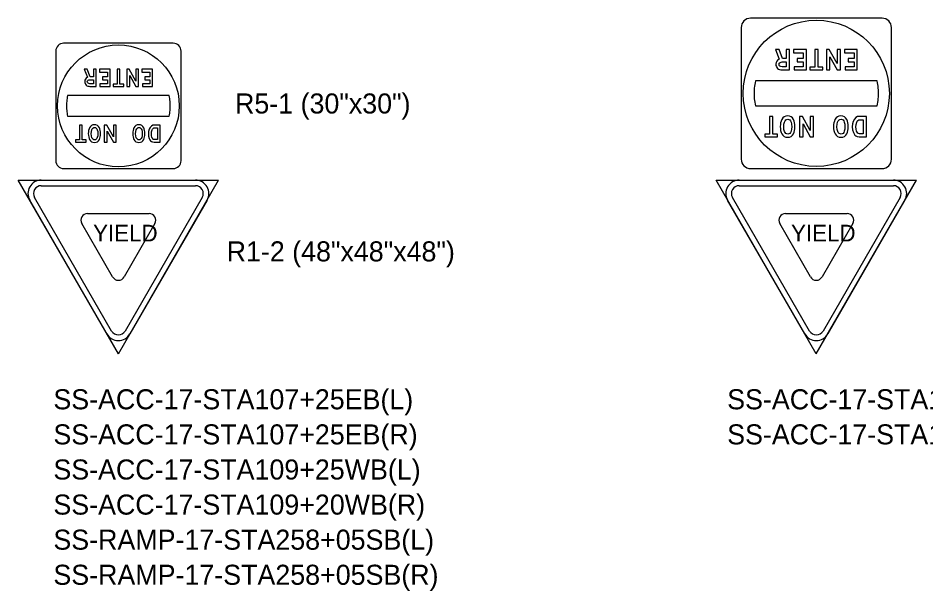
# Model space of a CAD drawing. Extents: x 620856.8 to 620948.6, y 415598.8 to 415658.2.
# Drawn here: x 620859.34 to 620877.45, y 415616.28 to 415627.7 of the extents above; entities that cross this region are included whole.
import ezdxf

# ---------------------------------------------------------------- set-up
doc = ezdxf.new("R2010")
doc.units = 0
doc.layers.add('SIGNS', color=7, linetype='Continuous')

msp = doc.modelspace()

# ---------------------------------------------------------------- linework, layer by layer
at = {"layer": 'SIGNS'}
for p, q in [((620876.575, 415627.702), (620873.95, 415627.702)), ((620876.575, 415627.702), (620873.95, 415627.702)), ((620873.762, 415627.514), (620873.762, 415624.889)), ((620873.762, 415627.514), (620873.762, 415624.889)), ((620876.762, 415624.889), (620876.762, 415627.514)), ((620876.762, 415624.889), (620876.762, 415627.514)), ((620862.431, 415627.202), (620860.243, 415627.202)), ((620862.431, 415627.202), (620860.243, 415627.202)), ((620860.087, 415627.045), (620860.087, 415624.858)), ((620860.087, 415627.045), (620860.087, 415624.858)), ((620862.587, 415624.858), (620862.587, 415627.045)), ((620862.587, 415624.858), (620862.587, 415627.045)), ((620874.046, 415626.45), (620874.04, 415626.415)), ((620876.478, 415626.45), (620874.046, 415626.45)), ((620876.485, 415626.415), (620876.478, 415626.45)), ((620874.023, 415626.273), (620874.022, 415626.237)), ((620874.025, 415626.308), (620874.023, 415626.273)), ((620874.029, 415626.344), (620874.025, 415626.308)), ((620874.034, 415626.379), (620874.029, 415626.344)), ((620874.04, 415626.415), (620874.034, 415626.379)), ((620876.491, 415626.379), (620876.485, 415626.415)), ((620876.496, 415626.344), (620876.491, 415626.379)), ((620876.499, 415626.308), (620876.496, 415626.344)), ((620876.502, 415626.273), (620876.499, 415626.308)), ((620876.503, 415626.237), (620876.502, 415626.273)), ((620860.313, 415626.1), (620860.309, 415626.071)), ((620860.318, 415626.129), (620860.313, 415626.1)), ((620860.323, 415626.158), (620860.318, 415626.129)), ((620862.35, 415626.158), (620860.323, 415626.158)), ((620862.356, 415626.129), (620862.35, 415626.158)), ((620862.36, 415626.1), (620862.356, 415626.129)), ((620862.365, 415626.071), (620862.36, 415626.1)), ((620874.022, 415626.237), (620874.021, 415626.202)), ((620874.021, 415626.202), (620874.022, 415626.166)), ((620874.022, 415626.166), (620874.023, 415626.13)), ((620874.023, 415626.13), (620874.025, 415626.095)), ((620874.025, 415626.095), (620874.029, 415626.059)), ((620876.496, 415626.059), (620876.499, 415626.095)), ((620876.499, 415626.095), (620876.502, 415626.13)), ((620876.502, 415626.13), (620876.503, 415626.166)), ((620876.504, 415626.201), (620876.503, 415626.237)), ((620876.503, 415626.166), (620876.504, 415626.201)), ((620860.304, 415626.011), (620860.303, 415625.981)), ((620860.303, 415625.981), (620860.303, 415625.952)), ((620860.303, 415625.952), (620860.303, 415625.922)), ((620860.303, 415625.922), (620860.304, 415625.892)), ((620860.306, 415626.041), (620860.304, 415626.011)), ((620860.309, 415626.071), (620860.306, 415626.041)), ((620862.368, 415626.041), (620862.365, 415626.071)), ((620862.37, 415626.011), (620862.368, 415626.041)), ((620862.371, 415625.981), (620862.37, 415626.011)), ((620862.37, 415625.892), (620862.371, 415625.922)), ((620862.371, 415625.951), (620862.371, 415625.981)), ((620862.371, 415625.922), (620862.371, 415625.951)), ((620874.029, 415626.059), (620874.034, 415626.024)), ((620874.034, 415626.024), (620874.04, 415625.988)), ((620874.04, 415625.988), (620874.046, 415625.954)), ((620874.046, 415625.954), (620876.478, 415625.954)), ((620876.478, 415625.954), (620876.485, 415625.988)), ((620876.485, 415625.988), (620876.491, 415626.024)), ((620876.491, 415626.024), (620876.496, 415626.059)), ((620860.304, 415625.892), (620860.306, 415625.863)), ((620860.306, 415625.863), (620860.309, 415625.833)), ((620860.309, 415625.833), (620860.313, 415625.804)), ((620860.313, 415625.804), (620860.318, 415625.774)), ((620860.318, 415625.774), (620860.323, 415625.745)), ((620860.323, 415625.745), (620862.35, 415625.745)), ((620862.35, 415625.745), (620862.356, 415625.774)), ((620862.356, 415625.774), (620862.36, 415625.804)), ((620862.36, 415625.804), (620862.365, 415625.833)), ((620862.365, 415625.833), (620862.368, 415625.863)), ((620862.368, 415625.863), (620862.37, 415625.892)), ((620860.243, 415624.702), (620862.431, 415624.702)), ((620860.243, 415624.702), (620862.431, 415624.702)), ((620873.95, 415624.702), (620876.575, 415624.702)), ((620873.95, 415624.702), (620876.575, 415624.702)), ((620859.337, 415624.471), (620863.337, 415624.471)), ((620861.337, 415621.007), (620859.337, 415624.471)), ((620859.799, 415624.471), (620862.875, 415624.471)), ((620861.337, 415621.007), (620863.337, 415624.471)), ((620873.262, 415624.471), (620877.262, 415624.471)), ((620875.262, 415621.007), (620873.262, 415624.471)), ((620873.724, 415624.471), (620876.8, 415624.471)), ((620875.262, 415621.007), (620877.262, 415624.471)), ((620859.799, 415624.36), (620862.875, 415624.36)), ((620873.724, 415624.36), (620876.8, 415624.36)), ((620861.202, 415621.462), (620859.664, 415624.126)), ((620863.01, 415624.126), (620861.472, 415621.462)), ((620875.128, 415621.462), (620873.59, 415624.126)), ((620876.935, 415624.126), (620875.397, 415621.462)), ((620861.106, 415621.407), (620859.568, 415624.071)), ((620863.106, 415624.071), (620861.568, 415621.407)), ((620875.031, 415621.407), (620873.493, 415624.071)), ((620877.031, 415624.071), (620875.493, 415621.407)), ((620860.722, 415623.804), (620861.951, 415623.804)), ((620874.648, 415623.804), (620875.877, 415623.804)), ((620861.221, 415622.54), (620860.607, 415623.604)), ((620862.067, 415623.604), (620861.452, 415622.54)), ((620875.147, 415622.54), (620874.533, 415623.604)), ((620875.992, 415623.604), (620875.378, 415622.54))]:
    msp.add_line(p, q, dxfattribs=at)
for points in [[(620874.727, 415627.077), (620874.663, 415627.077), (620874.663, 415626.897), (620874.585, 415626.897), (620874.518, 415627.077), (620874.447, 415627.077), (620874.52, 415626.886), (620874.494, 415626.868), (620874.473, 415626.843), (620874.46, 415626.814), (620874.456, 415626.783), (620874.458, 415626.759), (620874.465, 415626.737), (620874.476, 415626.718), (620874.491, 415626.7), (620874.51, 415626.686), (620874.531, 415626.676), (620874.554, 415626.67), (620874.579, 415626.668), (620874.727, 415626.668), (620874.727, 415627.077)], [(620874.663, 415626.828), (620874.663, 415626.732), (620874.578, 415626.732), (620874.555, 415626.735), (620874.536, 415626.745), (620874.523, 415626.76), (620874.519, 415626.78), (620874.524, 415626.801), (620874.538, 415626.817), (620874.558, 415626.826), (620874.581, 415626.828), (620874.663, 415626.828)], [(620860.891, 415626.681), (620860.837, 415626.681), (620860.837, 415626.531), (620860.772, 415626.531), (620860.717, 415626.681), (620860.657, 415626.681), (620860.718, 415626.522), (620860.696, 415626.507), (620860.679, 415626.487), (620860.668, 415626.462), (620860.665, 415626.436), (620860.667, 415626.416), (620860.672, 415626.398), (620860.681, 415626.382), (620860.694, 415626.367), (620860.71, 415626.355), (620860.727, 415626.347), (620860.746, 415626.342), (620860.767, 415626.34), (620860.891, 415626.341), (620860.891, 415626.681)], [(620860.837, 415626.474), (620860.837, 415626.394), (620860.766, 415626.394), (620860.748, 415626.396), (620860.732, 415626.404), (620860.721, 415626.417), (620860.717, 415626.434), (620860.721, 415626.451), (620860.733, 415626.465), (620860.75, 415626.472), (620860.769, 415626.474), (620860.837, 415626.474)], [(620874.543, 415625.539), (620874.545, 415625.496), (620874.551, 415625.458), (620874.56, 415625.424), (620874.573, 415625.395), (620874.594, 415625.365), (620874.621, 415625.344), (620874.654, 415625.331), (620874.692, 415625.327), (620874.728, 415625.331), (620874.76, 415625.344), (620874.786, 415625.366), (620874.807, 415625.397), (620874.819, 415625.426), (620874.828, 415625.459), (620874.834, 415625.496), (620874.836, 415625.536), (620874.834, 415625.578), (620874.828, 415625.616), (620874.819, 415625.65), (620874.807, 415625.679), (620874.786, 415625.711), (620874.759, 415625.733), (620874.726, 415625.747), (620874.688, 415625.751), (620874.652, 415625.747), (620874.62, 415625.733), (620874.594, 415625.711), (620874.572, 415625.68), (620874.56, 415625.65), (620874.55, 415625.617), (620874.545, 415625.58), (620874.543, 415625.539)], [(620875.606, 415625.539), (620875.608, 415625.496), (620875.613, 415625.458), (620875.623, 415625.424), (620875.636, 415625.395), (620875.657, 415625.365), (620875.684, 415625.344), (620875.717, 415625.331), (620875.755, 415625.327), (620875.791, 415625.331), (620875.823, 415625.344), (620875.849, 415625.366), (620875.87, 415625.397), (620875.882, 415625.426), (620875.891, 415625.459), (620875.897, 415625.496), (620875.898, 415625.536), (620875.897, 415625.578), (620875.891, 415625.616), (620875.882, 415625.65), (620875.87, 415625.679), (620875.848, 415625.711), (620875.822, 415625.733), (620875.789, 415625.747), (620875.751, 415625.751), (620875.715, 415625.747), (620875.683, 415625.733), (620875.657, 415625.711), (620875.635, 415625.68), (620875.622, 415625.65), (620875.613, 415625.617), (620875.608, 415625.58), (620875.606, 415625.539)], [(620876.118, 415625.335), (620876.261, 415625.335), (620876.261, 415625.743), (620876.111, 415625.743), (620876.084, 415625.737), (620876.054, 415625.719), (620876.022, 415625.685), (620875.999, 415625.643), (620875.986, 415625.593), (620875.981, 415625.534), (620875.986, 415625.476), (620876.002, 415625.422), (620876.017, 415625.392), (620876.034, 415625.369), (620876.054, 415625.352), (620876.077, 415625.34), (620876.118, 415625.335)], [(620860.737, 415625.399), (620860.739, 415625.364), (620860.744, 415625.332), (620860.751, 415625.304), (620860.762, 415625.28), (620860.78, 415625.255), (620860.803, 415625.237), (620860.83, 415625.226), (620860.861, 415625.222), (620860.892, 415625.226), (620860.918, 415625.237), (620860.94, 415625.255), (620860.957, 415625.281), (620860.968, 415625.305), (620860.975, 415625.333), (620860.98, 415625.363), (620860.981, 415625.397), (620860.98, 415625.432), (620860.975, 415625.463), (620860.968, 415625.492), (620860.957, 415625.516), (620860.939, 415625.543), (620860.917, 415625.561), (620860.89, 415625.573), (620860.859, 415625.576), (620860.828, 415625.573), (620860.802, 415625.562), (620860.78, 415625.543), (620860.762, 415625.517), (620860.751, 415625.492), (620860.743, 415625.464), (620860.739, 415625.433), (620860.737, 415625.399)], [(620861.623, 415625.399), (620861.625, 415625.364), (620861.629, 415625.332), (620861.637, 415625.304), (620861.648, 415625.28), (620861.666, 415625.255), (620861.688, 415625.237), (620861.715, 415625.226), (620861.747, 415625.222), (620861.778, 415625.226), (620861.804, 415625.237), (620861.825, 415625.255), (620861.843, 415625.281), (620861.853, 415625.305), (620861.861, 415625.333), (620861.865, 415625.363), (620861.867, 415625.397), (620861.865, 415625.432), (620861.861, 415625.463), (620861.853, 415625.492), (620861.843, 415625.516), (620861.825, 415625.543), (620861.803, 415625.561), (620861.776, 415625.573), (620861.744, 415625.576), (620861.714, 415625.573), (620861.688, 415625.562), (620861.665, 415625.543), (620861.648, 415625.517), (620861.637, 415625.492), (620861.629, 415625.464), (620861.625, 415625.433), (620861.623, 415625.399)], [(620862.05, 415625.229), (620862.169, 415625.229), (620862.169, 415625.57), (620862.044, 415625.57), (620862.021, 415625.565), (620861.996, 415625.549), (620861.97, 415625.521), (620861.951, 415625.486), (620861.939, 415625.444), (620861.936, 415625.395), (620861.94, 415625.347), (620861.953, 415625.302), (620861.966, 415625.277), (620861.98, 415625.258), (620861.997, 415625.243), (620862.015, 415625.234), (620862.05, 415625.229)], [(620874.611, 415625.534), (620874.615, 415625.587), (620874.626, 415625.629), (620874.638, 415625.654), (620874.653, 415625.671), (620874.672, 415625.681), (620874.694, 415625.684), (620874.715, 415625.681), (620874.732, 415625.671), (620874.747, 415625.654), (620874.758, 415625.629), (620874.768, 415625.588), (620874.771, 415625.537), (620874.768, 415625.487), (620874.758, 415625.445), (620874.747, 415625.421), (620874.733, 415625.403), (620874.715, 415625.393), (620874.695, 415625.389), (620874.673, 415625.393), (620874.654, 415625.402), (620874.638, 415625.418), (620874.626, 415625.44), (620874.615, 415625.482), (620874.611, 415625.534)], [(620875.674, 415625.534), (620875.678, 415625.587), (620875.688, 415625.629), (620875.701, 415625.654), (620875.716, 415625.671), (620875.735, 415625.681), (620875.756, 415625.684), (620875.777, 415625.681), (620875.795, 415625.671), (620875.81, 415625.654), (620875.821, 415625.629), (620875.831, 415625.588), (620875.834, 415625.537), (620875.831, 415625.487), (620875.821, 415625.445), (620875.81, 415625.421), (620875.795, 415625.403), (620875.778, 415625.393), (620875.758, 415625.389), (620875.736, 415625.393), (620875.717, 415625.402), (620875.701, 415625.418), (620875.689, 415625.44), (620875.678, 415625.482), (620875.674, 415625.534)], [(620876.131, 415625.676), (620876.197, 415625.676), (620876.197, 415625.396), (620876.125, 415625.396), (620876.106, 415625.399), (620876.09, 415625.409), (620876.077, 415625.426), (620876.066, 415625.449), (620876.056, 415625.489), (620876.053, 415625.536), (620876.057, 415625.583), (620876.068, 415625.625), (620876.08, 415625.647), (620876.094, 415625.663), (620876.111, 415625.673), (620876.131, 415625.676)], [(620860.794, 415625.395), (620860.797, 415625.439), (620860.806, 415625.475), (620860.816, 415625.495), (620860.829, 415625.509), (620860.845, 415625.518), (620860.863, 415625.521), (620860.88, 415625.518), (620860.895, 415625.509), (620860.907, 415625.495), (620860.916, 415625.475), (620860.925, 415625.44), (620860.928, 415625.398), (620860.925, 415625.356), (620860.916, 415625.321), (620860.907, 415625.301), (620860.895, 415625.286), (620860.881, 415625.278), (620860.864, 415625.275), (620860.846, 415625.277), (620860.83, 415625.285), (620860.817, 415625.299), (620860.807, 415625.317), (620860.797, 415625.352), (620860.794, 415625.395)], [(620861.68, 415625.395), (620861.683, 415625.439), (620861.692, 415625.475), (620861.702, 415625.495), (620861.715, 415625.509), (620861.73, 415625.518), (620861.749, 415625.521), (620861.766, 415625.518), (620861.781, 415625.509), (620861.793, 415625.495), (620861.802, 415625.475), (620861.811, 415625.44), (620861.813, 415625.398), (620861.811, 415625.356), (620861.802, 415625.321), (620861.793, 415625.301), (620861.781, 415625.286), (620861.767, 415625.278), (620861.75, 415625.275), (620861.731, 415625.277), (620861.716, 415625.285), (620861.703, 415625.299), (620861.692, 415625.317), (620861.683, 415625.352), (620861.68, 415625.395)], [(620862.06, 415625.514), (620862.116, 415625.514), (620862.116, 415625.28), (620862.055, 415625.28), (620862.04, 415625.283), (620862.027, 415625.291), (620862.016, 415625.305), (620862.007, 415625.324), (620861.998, 415625.358), (620861.995, 415625.397), (620861.999, 415625.436), (620862.008, 415625.471), (620862.018, 415625.49), (620862.03, 415625.503), (620862.044, 415625.511), (620862.06, 415625.514)]]:
    msp.add_lwpolyline(points, dxfattribs=at)
for points in [[(620875.064, 415627.077), (620874.808, 415627.077), (620874.808, 415627.013), (620875, 415627.013), (620875, 415626.9), (620874.879, 415626.9), (620874.879, 415626.828), (620875, 415626.828), (620875, 415626.732), (620874.821, 415626.732), (620874.821, 415626.668), (620875.064, 415626.668)], [(620875.297, 415627.077), (620875.232, 415627.077), (620875.232, 415626.722), (620875.135, 415626.722), (620875.135, 415626.668), (620875.391, 415626.668), (620875.391, 415626.722), (620875.297, 415626.722)], [(620875.743, 415627.077), (620875.679, 415627.077), (620875.679, 415626.798), (620875.521, 415627.077), (620875.463, 415627.077), (620875.463, 415626.668), (620875.535, 415626.668), (620875.535, 415626.928), (620875.679, 415626.668), (620875.743, 415626.668)], [(620876.079, 415627.077), (620875.824, 415627.077), (620875.824, 415627.013), (620876.016, 415627.013), (620876.016, 415626.9), (620875.895, 415626.9), (620875.895, 415626.828), (620876.016, 415626.828), (620876.016, 415626.732), (620875.837, 415626.732), (620875.837, 415626.668), (620876.079, 415626.668)], [(620861.171, 415626.681), (620860.958, 415626.681), (620860.958, 415626.627), (620861.118, 415626.627), (620861.118, 415626.534), (620861.017, 415626.534), (620861.017, 415626.474), (620861.118, 415626.474), (620861.118, 415626.394), (620860.969, 415626.394), (620860.969, 415626.34), (620861.171, 415626.34)], [(620861.366, 415626.681), (620861.311, 415626.681), (620861.311, 415626.385), (620861.231, 415626.385), (620861.231, 415626.34), (620861.444, 415626.34), (620861.444, 415626.385), (620861.366, 415626.385)], [(620861.737, 415626.681), (620861.684, 415626.681), (620861.684, 415626.448), (620861.552, 415626.681), (620861.504, 415626.681), (620861.504, 415626.34), (620861.564, 415626.34), (620861.564, 415626.557), (620861.684, 415626.34), (620861.737, 415626.34)], [(620862.018, 415626.681), (620861.805, 415626.681), (620861.805, 415626.627), (620861.965, 415626.627), (620861.965, 415626.534), (620861.864, 415626.534), (620861.864, 415626.474), (620861.965, 415626.474), (620861.965, 415626.394), (620861.816, 415626.394), (620861.816, 415626.34), (620862.018, 415626.34)], [(620874.394, 415625.743), (620874.329, 415625.743), (620874.329, 415625.389), (620874.233, 415625.389), (620874.233, 415625.335), (620874.488, 415625.335), (620874.488, 415625.389), (620874.394, 415625.389)], [(620875.206, 415625.743), (620875.142, 415625.743), (620875.142, 415625.464), (620874.984, 415625.743), (620874.926, 415625.743), (620874.926, 415625.335), (620874.998, 415625.335), (620874.998, 415625.595), (620875.142, 415625.335), (620875.206, 415625.335)], [(620860.613, 415625.57), (620860.559, 415625.57), (620860.559, 415625.274), (620860.479, 415625.274), (620860.479, 415625.229), (620860.692, 415625.229), (620860.692, 415625.274), (620860.613, 415625.274)], [(620861.29, 415625.57), (620861.237, 415625.57), (620861.237, 415625.337), (620861.105, 415625.57), (620861.056, 415625.57), (620861.056, 415625.229), (620861.116, 415625.229), (620861.116, 415625.446), (620861.237, 415625.229), (620861.29, 415625.229)]]:
    msp.add_lwpolyline(points, close=True, dxfattribs=at)
for centre, radius in [((620875.262, 415626.202), 1.458), ((620861.337, 415625.952), 1.215)]:
    msp.add_circle(centre, radius, dxfattribs=at)
for centre, radius, start, end in [((620873.95, 415627.514), 0.187, 90.0001, 180.0003), ((620873.95, 415627.514), 0.187, 90.0001, 180.0003), ((620876.575, 415627.514), 0.187, 359.9998, 90.0001), ((620876.575, 415627.514), 0.187, 359.9998, 90.0001), ((620860.243, 415627.045), 0.156, 90.0001, 180.0003), ((620860.243, 415627.045), 0.156, 90.0001, 180.0003), ((620862.431, 415627.045), 0.156, 359.9998, 90.0001), ((620862.431, 415627.045), 0.156, 359.9998, 90.0001), ((620860.243, 415624.858), 0.156, 180, 270.0002), ((620860.243, 415624.858), 0.156, 180, 270.0002), ((620862.431, 415624.858), 0.156, 270.0002, 359.9998), ((620862.431, 415624.858), 0.156, 270.0002, 359.9998), ((620862.431, 415624.858), 0.156, 270.0002, 359.9998), ((620873.95, 415624.889), 0.187, 180, 270.0002), ((620873.95, 415624.889), 0.187, 180, 270.0002), ((620876.575, 415624.889), 0.187, 270.0002, 359.9998), ((620876.575, 415624.889), 0.187, 270.0002, 359.9998), ((620876.575, 415624.889), 0.187, 270.0002, 359.9998), ((620859.799, 415624.204), 0.267, 90, 210), ((620862.875, 415624.204), 0.267, 330, 90), ((620873.724, 415624.204), 0.267, 90, 210), ((620876.8, 415624.204), 0.267, 330, 90), ((620859.799, 415624.204), 0.156, 90, 210), ((620862.875, 415624.204), 0.156, 330, 90), ((620873.724, 415624.204), 0.156, 90, 210), ((620876.8, 415624.204), 0.156, 330, 90), ((620860.722, 415623.671), 0.133, 90, 210), ((620861.951, 415623.671), 0.133, 330, 90), ((620874.648, 415623.671), 0.133, 90, 210), ((620875.877, 415623.671), 0.133, 330, 90), ((620861.337, 415622.607), 0.133, 210, 330), ((620875.262, 415622.607), 0.133, 210, 330), ((620861.337, 415621.54), 0.267, 210, 330), ((620861.337, 415621.54), 0.156, 210, 330), ((620875.262, 415621.54), 0.267, 210, 330), ((620875.262, 415621.54), 0.156, 210, 330)]:
    msp.add_arc(centre, radius, start, end, dxfattribs=at)

# ---------------------------------------------------------------- texts
for s, p in [('R5-1 (30"x30")', (620863.664, 415625.8)), ('R1-2 (48"x48"x48")', (620863.497, 415622.85)), ('SS-ACC-17-STA107+25EB(L)', (620860.04, 415619.9)), ('SS-ACC-17-STA130+10EB', (620873.484, 415619.9)), ('SS-ACC-17-STA107+25EB(R)', (620860.04, 415619.2)), ('SS-ACC-17-STA131+10EB', (620873.484, 415619.2)), ('SS-ACC-17-STA109+25WB(L)', (620860.04, 415618.5)), ('SS-ACC-17-STA109+20WB(R)', (620860.04, 415617.8)), ('SS-RAMP-17-STA258+05SB(L)', (620860.04, 415617.1)), ('SS-RAMP-17-STA258+05SB(R)', (620860.04, 415616.4))]:
    msp.add_text(s, height=0.4, rotation=0, dxfattribs=at).set_placement(p)
for p in [(620860.832, 415623.248), (620874.758, 415623.248)]:
    msp.add_text('YIELD', height=0.3333, dxfattribs=at).set_placement(p)

doc.saveas('drawing.dxf')
